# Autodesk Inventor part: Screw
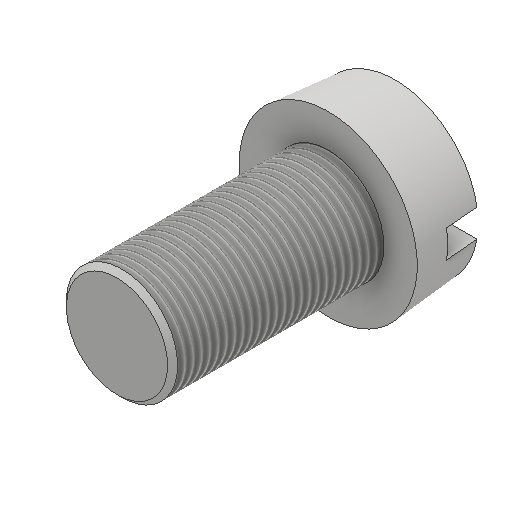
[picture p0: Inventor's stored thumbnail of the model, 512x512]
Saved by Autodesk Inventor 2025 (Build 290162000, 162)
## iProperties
Created: 2016-05
Part Number: Screw
Material: Generic
Document SubType Name: Modeling
Designer: CADCIM
Density: 1 g/cm^3
Appearance: Default
Author: CADCIM
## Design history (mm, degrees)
sketch "Sketch1"
  geometry: C1 r 16 at (0, 0); 1 further point
  constraints: 1 centre point, 1 coincident
  dimensions: "d0" = 32 diameter of C1
extrude "Extrusion1" new body sketch "Sketch1" distance "d1" = 12; taper "d2" = -5 deg
sketch "Sketch2"
  geometry: C1 r 10 at (0, 0); 1 further point
  constraints: 1 centre point, 1 coincident
  dimensions: "d4" = 20 diameter of C1
extrude "Extrusion2" join sketch "Sketch2" distance "d5" = 38; taper "d6" = 0 deg
workplane "Work Plane1"
thread "Thread1" dims "d10" = 10, "d11" = 0
chamfer "Chamfer1" distance "d12" = 0.9; stored, may be unused: second distance "d13" = 2, angle "d14" = 45 deg
sketch "Sketch4"
  geometry: L1 (-19.014, -2.5)-(20.179, -2.5); L2 (20.179, -2.5)-(20.179, 2.5); L3 (20.179, 2.5)-(-19.014, 2.5); L4 (-19.014, 2.5)-(-19.014, -2.5); L5 (0, 0)-(-19.039, 0)
  constraints: 10 end point, 2 horizontal, 2 parallel, 1 perpendicular, 1 other
  dimensions: "d15" = 5 distance of L3.end L1.start
extrude "Extrusion4" cut sketch "Sketch4" distance "d16" = 6; taper "d17" = 0 deg
body "Solid1"
